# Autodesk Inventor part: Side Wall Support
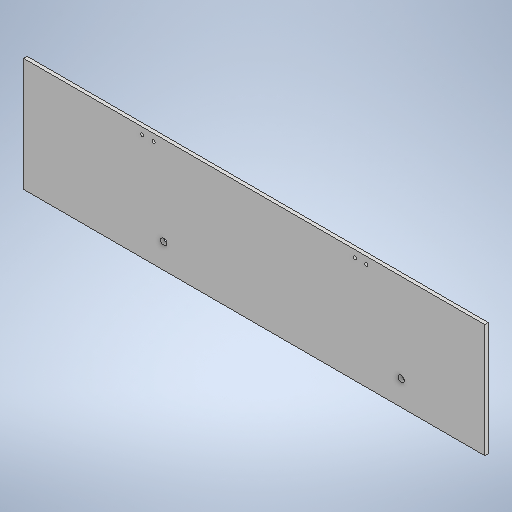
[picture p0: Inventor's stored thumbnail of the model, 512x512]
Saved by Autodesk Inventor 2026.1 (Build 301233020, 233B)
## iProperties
Created: 2026-10
Part Number: Side Wall Support
Material: Generic
Document SubType Name: Modeling
Designer: hp
Density: 1 g/cm^3
Appearance: Default
Author: hp
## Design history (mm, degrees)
sketch "Sketch1"
  geometry: L1 (0, 0)-(700, 0); L2 (700, 160)-(0, 160); L3 (0, 160)-(0, 0); L4 (700, 160)-(700, 0); L5 (50, 160)-(50, 0)
  constraints: 10 end point, 2 point on line, 1 horizontal, 1 parallel, 1 perpendicular, 1 vertical
  dimensions: "d28" = 700 distance of L2.start L2.end; "d29" = 160 distance of L2.end L1.start; "d48" = 50 distance between parallel lines of L3 L5
extrude "Extrusion2" new body sketch "Sketch1" distance "d23" = 5; taper "d24" = 0 deg
sketch "Sketch4"
  geometry: 4 further points
hole "Hole1" sketch "Sketch4" at (217, 150), (233, 150), (517, 150), (533, 150) diameter "d49" = 4.5; stored, may be unused: countersink angle "d53" = 90 deg, drill point angle "d55" = 0 deg; dims "d50" = 6, "d51" = 4, "d52" = 2, "d54" = 8
sketch "Sketch5"
  geometry: 2 further points
hole "Hole2" sketch "Sketch5" at (-247.5, 35), (-582.5, 35) diameter "d56" = 9; stored, may be unused: countersink angle "d60" = 90 deg, drill point angle "d62" = 0 deg; dims "d57" = 6, "d58" = 4, "d59" = 2, "d61" = 8
body "Solid2"
